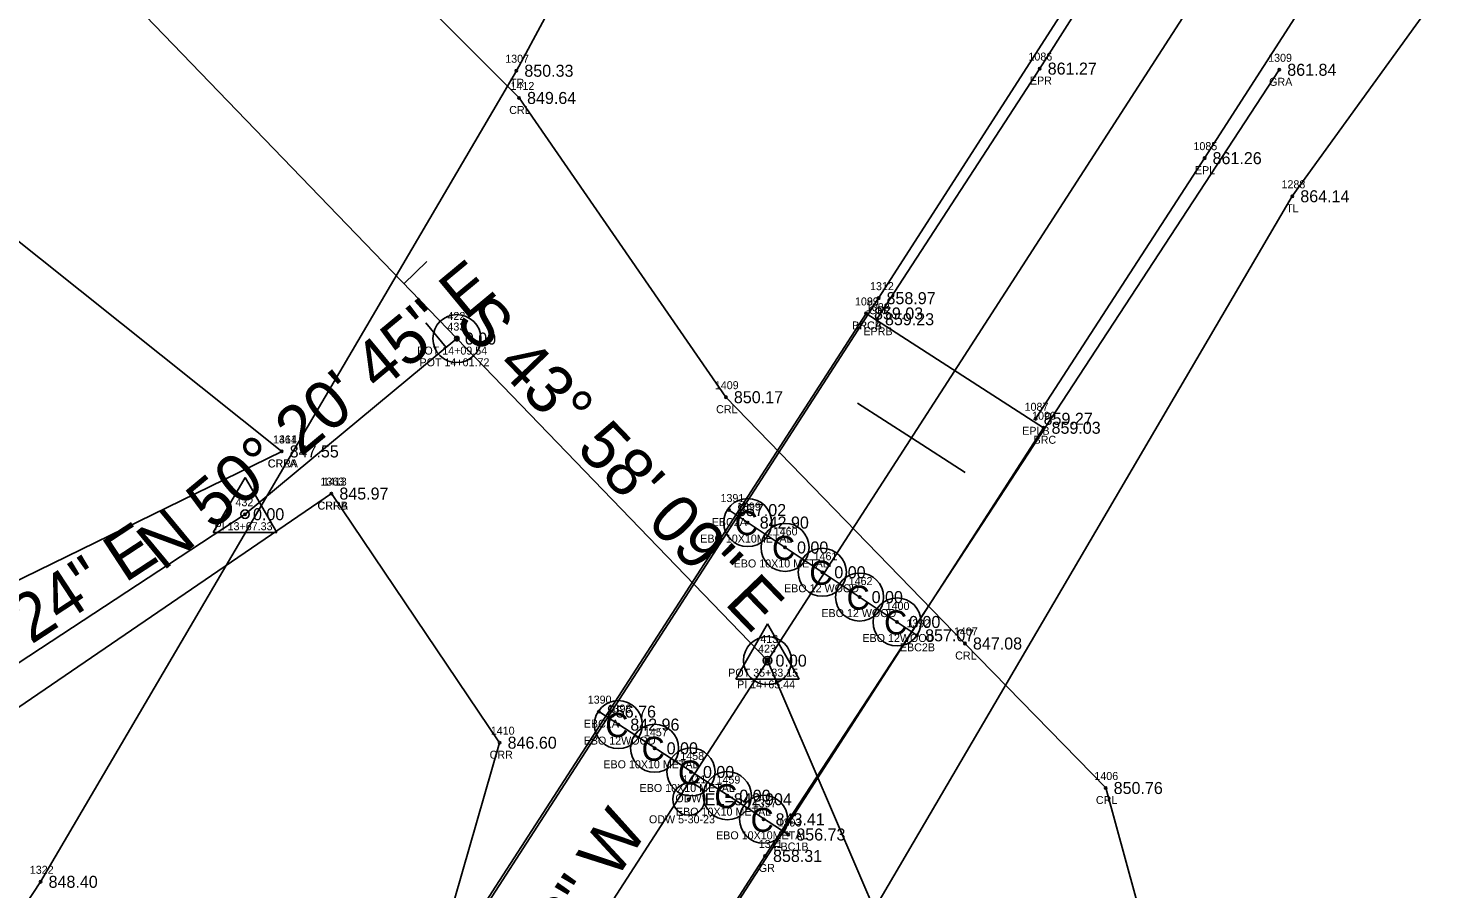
# Model space of a CAD drawing. Extents: x 1393163 to 1398407, y 1072670 to 1074651.
# Drawn here: x 1395829.2 to 1396005.3, y 1073941.1 to 1074048.6 of the extents above; entities that cross this region are included whole.
import ezdxf

# ---------------------------------------------------------------- set-up
doc = ezdxf.new("R2010")
doc.units = 0
for name, color, linetype in [('RD_EX_Bridge', 7, 'Continuous'), ('RD_EX_Bridge_txCode', 7, 'Continuous'), ('RD_EX_GuardRail', 7, 'Continuous'), ('RD_EX_GuardRail_txCode', 7, 'Continuous'), ('RD_EX_H2O', 7, 'Continuous'), ('RD_EX_H2O_txCode', 7, 'Continuous'), ('RD_EX_Road', 7, 'Continuous'), ('RD_EX_Road_txCode', 7, 'Continuous'), ('RD_EX_TX_Bridge_ELEV', 7, 'Continuous'), ('RD_EX_TX_GuardRail_ELEV', 7, 'Continuous'), ('RD_EX_TX_H2O_ELEV', 7, 'Continuous'), ('RD_EX_TX_Road_ELEV', 7, 'Continuous'), ('RD_EX_TX_VEG_ELEV', 7, 'Continuous'), ('RD_EX_VEG', 7, 'Continuous'), ('RD_EX_VEG_txCode', 7, 'Continuous'), ('RD_HC_Cl', 7, 'Continuous'), ('RD_HC_Data', 7, 'Continuous'), ('RD_HC_Data_Tic', 7, 'Continuous'), ('RD_HC_Survey_ELEV', 7, 'Continuous'), ('RD_HC_txCode', 7, 'Continuous'), ('RD_SMD_Locator', 7, 'Continuous')]:
    doc.layers.add(name, color=color, linetype=linetype)

msp = doc.modelspace()

# ---------------------------------------------------------------- linework, layer by layer
at = {"layer": 'RD_EX_Bridge'}
for p, q in [((1395916.79, 1073988.44), (1395940.29, 1073972.79)), ((1395900.53, 1073963.26), (1395924.2, 1073947.91))]:
    msp.add_line(p, q, dxfattribs=at)
msp.add_lwpolyline([(1395933.91, 1074013), (1395956.09, 1073998.72), (1395891.08, 1073897.92), (1395868.85, 1073912.35), (1395933.91, 1074013)], dxfattribs=at)
for centre in [(1395919.13, 1073986.88), (1395923.79, 1073983.77), (1395928.45, 1073980.67), (1395933.11, 1073977.57), (1395937.79, 1073974.46), (1395902.96, 1073961.64), (1395907.5, 1073958.68), (1395912.04, 1073955.72), (1395916.58, 1073952.76), (1395921.11, 1073949.81)]:
    msp.add_circle(centre, 3, dxfattribs=at)
at = {"layer": 'RD_EX_GuardRail'}
for points in [[(1396016.92, 1074142.31), (1395982.2, 1074087.63), (1395935.47, 1074014.91), (1395869.54, 1073912.84), (1395852.29, 1073888.13)], [(1395985.54, 1074043.44), (1395921.29, 1073945.23), (1395889.11, 1073895.32), (1395862.94, 1073850.57)]]:
    msp.add_lwpolyline(points, dxfattribs=at)
at = {"layer": 'RD_EX_H2O'}
for points in [[(1395994.31, 1073862.14), (1395977.4, 1073904.27), (1395963.85, 1073953.72), (1395946.27, 1073971.77), (1395916.4, 1074002.54), (1395890.56, 1074039.92), (1395847.47, 1074083.11), (1395801.13, 1074111.33), (1395786.04, 1074175.28), (1395797.31, 1074211.4), (1395811.45, 1074270.55), (1395842.05, 1074318.44), (1395857.75, 1074334.75)], [(1395860.9, 1073995.76), (1395815.67, 1074031.86), (1395776.21, 1074053.68), (1395741.83, 1074102.21), (1395737.14, 1074094.97), (1395730.93, 1074079.84), (1395706.27, 1074079.36), (1395688.76, 1074107.43)], [(1395860.9, 1073995.76), (1395800.01, 1073966.01), (1395776.82, 1073934.08), (1395764.26, 1073892.72), (1395729.42, 1073844.79)], [(1395867.11, 1073990.5), (1395809.63, 1073951.26), (1395794.76, 1073924.94), (1395779.33, 1073882.65), (1395735.99, 1073839.85)], [(1395952, 1073840.27), (1395936.35, 1073875.41), (1395908.33, 1073913.75), (1395880.62, 1073933.3), (1395888.13, 1073959.38), (1395867.11, 1073990.5)]]:
    msp.add_lwpolyline(points, dxfattribs=at)
for radius in [2, 0.15]:
    msp.add_circle((1395911.76, 1073952.31), radius, dxfattribs=at)
at = {"layer": 'RD_EX_Road'}
for points in [[(1396674.59, 1074386.64), (1396624.89, 1074395.26), (1396571.56, 1074398.48), (1396522.78, 1074397.7), (1396472.45, 1074394.9), (1396421.62, 1074390.65), (1396372.56, 1074384.52), (1396322.77, 1074374.54), (1396273.68, 1074359.26), (1396227.22, 1074339.05), (1396181.9, 1074313.32), (1396140.46, 1074283.11), (1396103.05, 1074249.25), (1396069.12, 1074211.4), (1396038.71, 1074171.59), (1396010.56, 1074129.17), (1395983.61, 1074087.64), (1395955.61, 1074043.59), (1395935.28, 1074012.28)], [(1396669.99, 1074363.58), (1396621.68, 1074371.65), (1396572.56, 1074374.92), (1396523.47, 1074374.03), (1396473.59, 1074371.37), (1396424.21, 1074367.31), (1396376.75, 1074361.05), (1396328.97, 1074351.54), (1396282.26, 1074337.09), (1396237.6, 1074317.67), (1396195.62, 1074293.72), (1396156.18, 1074264.82), (1396120.35, 1074232.59), (1396087.8, 1074196.98), (1396058.13, 1074158.17), (1396030.89, 1074117.17), (1396003.36, 1074074.62), (1395976.21, 1074032.4), (1395955.1, 1073999.84)]]:
    msp.add_lwpolyline(points, dxfattribs=at)
at = {"layer": 'RD_EX_VEG'}
for points in [[(1396352.77, 1074466.81), (1396307.45, 1074411.54), (1396264.81, 1074389.13), (1396223.65, 1074377.38), (1396189.41, 1074374.79), (1396152.48, 1074363.91), (1396104.93, 1074328.72), (1396084.67, 1074294.89), (1396058.15, 1074258), (1396032.64, 1074208.26), (1395942.76, 1074111.4), (1395907.95, 1074076.23), (1395890.22, 1074043.32), (1395830.78, 1073942), (1395722.32, 1073776.86), (1395650.71, 1073693.74), (1395598.01, 1073628.59), (1395527.38, 1073544.13)], [(1396669.03, 1074354.22), (1396616.02, 1074355.85), (1396573.77, 1074355.35), (1396526.61, 1074357.18), (1396479.56, 1074337.11), (1396434.19, 1074332.46), (1396381.24, 1074326.22), (1396336.08, 1074320.75), (1396275.81, 1074321.18), (1396244.15, 1074304.15), (1396202.15, 1074284.28), (1396132.57, 1074226.35), (1396098.86, 1074188.29), (1396070.36, 1074149.88), (1396041.42, 1074108.96), (1396016.11, 1074067.71), (1395987.17, 1074027.64), (1395903.34, 1073884.68), (1395772.36, 1073685.07), (1395714.36, 1073607.99), (1395678.43, 1073565.6), (1395644.57, 1073530.52), (1395600.99, 1073489.29), (1395561.12, 1073435.87)]]:
    msp.add_lwpolyline(points, dxfattribs=at)
at = {"layer": 'RD_HC_Cl'}
for p, q in [((1396041.52, 1074155.31), (1395744.21, 1073694.97)), ((1395765.48, 1074131.47), (1395882.79, 1074009.86)), ((1395856.32, 1073987.92), (1395882.79, 1074009.86)), ((1395882.79, 1074009.86), (1395921.6, 1073969.63)), ((1395794.66, 1073947.5), (1395856.32, 1073987.92)), ((1395921.6, 1073969.63), (1395997.49, 1073792.99))]:
    msp.add_line(p, q, dxfattribs=at)
at = {"layer": 'RD_HC_Data'}
for p, q in [((1395852.34, 1073985.62), (1395856.32, 1073992.5)), ((1395856.32, 1073992.5), (1395860.29, 1073985.62)), ((1395852.34, 1073985.62), (1395860.29, 1073985.62)), ((1395917.63, 1073967.33), (1395921.6, 1073974.21)), ((1395921.6, 1073974.21), (1395925.57, 1073967.33)), ((1395917.63, 1073967.33), (1395925.57, 1073967.33))]:
    msp.add_line(p, q, dxfattribs=at)
for centre, radius in [((1395882.79, 1074009.86), 3), ((1395882.79, 1074009.86), 3), ((1395882.79, 1074009.86), 0.282), ((1395882.79, 1074009.86), 0.282), ((1395856.32, 1073987.92), 0.529), ((1395921.6, 1073969.63), 3), ((1395921.6, 1073969.63), 0.529), ((1395921.6, 1073969.63), 0.282)]:
    msp.add_circle(centre, radius, dxfattribs=at)
at = {"layer": 'RD_HC_Data_Tic'}
for p, q in [((1395876.17, 1074016.72), (1395879.05, 1074019.5)), ((1395881.47, 1074008.76), (1395878.92, 1074011.84)), ((1395939.58, 1073997.47), (1395932.86, 1074001.81)), ((1395939.58, 1073997.47), (1395946.3, 1073993.13))]:
    msp.add_line(p, q, dxfattribs=at)
at = {"layer": 'RD_SMD_Locator'}
for centre in [(1395890.22, 1074043.32), (1395955.61, 1074043.59), (1395985.54, 1074043.44), (1395890.56, 1074039.92), (1395976.21, 1074032.4), (1395987.17, 1074027.64), (1395935.47, 1074014.91), (1395933.91, 1074013), (1395933.91, 1074013), (1395935.28, 1074012.28), (1395882.79, 1074009.86), (1395882.79, 1074009.86), (1395916.4, 1074002.54), (1395955.1, 1073999.84), (1395956.09, 1073998.72), (1395860.9, 1073995.76), (1395860.9, 1073995.76), (1395867.11, 1073990.5), (1395867.11, 1073990.5), (1395856.32, 1073987.92), (1395916.79, 1073988.44), (1395919.13, 1073986.88), (1395923.79, 1073983.77), (1395928.45, 1073980.67), (1395933.11, 1073977.57), (1395937.79, 1073974.46), (1395940.29, 1073972.79), (1395946.27, 1073971.77), (1395921.6, 1073969.63), (1395921.6, 1073969.63), (1395900.53, 1073963.26), (1395902.96, 1073961.64), (1395888.13, 1073959.38), (1395907.5, 1073958.68), (1395912.04, 1073955.72), (1395916.58, 1073952.76), (1395963.85, 1073953.72), (1395921.11, 1073949.81), (1395924.2, 1073947.91), (1395921.29, 1073945.23), (1395830.78, 1073942)]:
    msp.add_circle(centre, 0.15, dxfattribs=at)

# ---------------------------------------------------------------- texts
at = {"layer": 'RD_EX_Bridge'}
for p in [(1395917.5, 1073985.32), (1395922.16, 1073982.21), (1395926.82, 1073979.11), (1395931.48, 1073976.01), (1395936.16, 1073972.9), (1395901.33, 1073960.08), (1395905.87, 1073957.12), (1395910.41, 1073954.16), (1395914.95, 1073951.2), (1395919.48, 1073948.24)]:
    msp.add_text('C', height=3, dxfattribs=at).set_placement(p)
at = {"layer": 'RD_EX_Bridge_txCode'}
for s, p in [('1089', (1395932.53, 1074014)), ('1093', (1395932.53, 1074014)), ('BRCA', (1395932.17, 1074011)), ('BRCB', (1395932.19, 1074011)), ('1090', (1395954.66, 1073999.72)), ('BRC', (1395954.84, 1073996.72)), ('1391', (1395915.73, 1073989.44)), ('1399', (1395917.78, 1073988.38)), ('EBC2A', (1395914.63, 1073986.44)), ('1460', (1395922.38, 1073985.27)), ('EBO 10X10METAL', (1395913.2, 1073984.38)), ('1461', (1395927.36, 1073982.17)), ('EBO 10X10 METAL', (1395917.37, 1073981.27)), ('EBO 12 WOOD', (1395923.67, 1073978.17)), ('1462', (1395931.74, 1073979.07)), ('EBO 12 WOOD', (1395928.33, 1073975.07)), ('1400', (1395936.36, 1073975.96)), ('1392', (1395938.95, 1073973.79)), ('EBO 12WOOD', (1395933.46, 1073971.96)), ('EBC2B', (1395938.14, 1073970.79)), ('1390', (1395899.14, 1073964.26)), ('1398', (1395901.62, 1073963.14)), ('EBC1A', (1395898.65, 1073961.26)), ('EBO 12WOOD', (1395898.63, 1073959.14)), ('1457', (1395906.16, 1073960.18)), ('1458', (1395910.7, 1073957.22)), ('EBO 10X10 METAL', (1395901.09, 1073956.18)), ('1459', (1395915.23, 1073954.26)), ('EBO 10X10 METAL', (1395905.62, 1073953.22)), ('EBO 10X10 METAL', (1395910.16, 1073950.26)), ('1397', (1395919.76, 1073951.31)), ('1393', (1395922.86, 1073948.91)), ('EBO 10X10METAL', (1395915.18, 1073947.31)), ('EBC1B', (1395922.34, 1073945.91))]:
    msp.add_text(s, height=1, dxfattribs=at).set_placement(p)
at = {"layer": 'RD_EX_GuardRail_txCode'}
for s, p in [('1309', (1395984.15, 1074044.44)), ('GRA', (1395984.27, 1074041.44)), ('1312', (1395934.41, 1074015.91)), ('GR2', (1395934.25, 1074012.91)), ('1311', (1395920.51, 1073946.23)), ('GR', (1395920.51, 1073943.23))]:
    msp.add_text(s, height=1, dxfattribs=at).set_placement(p)
at = {"layer": 'RD_EX_H2O'}
msp.add_text('ODW', height=1, dxfattribs=at).set_placement((1395910.09, 1073951.94))
at = {"layer": 'RD_EX_H2O_txCode'}
for s, p in [('1412', (1395889.49, 1074040.92)), ('CRL', (1395889.33, 1074037.92)), ('1409', (1395915.02, 1074003.54)), ('CRL', (1395915.18, 1074000.54)), ('1361', (1395859.81, 1073996.76)), ('1414', (1395859.83, 1073996.76)), ('CRRA', (1395859.15, 1073993.76)), ('CRLA', (1395859.18, 1073993.76)), ('1363', (1395865.74, 1073991.5)), ('1413', (1395866.05, 1073991.5)), ('CRRA', (1395865.37, 1073988.5)), ('CRRB', (1395865.39, 1073988.5)), ('1407', (1395944.89, 1073972.77)), ('CRL', (1395945.05, 1073969.77)), ('1410', (1395887.03, 1073960.38)), ('CRR', (1395886.88, 1073957.38)), ('1411', (1395910.98, 1073954.31)), ('1406', (1395962.44, 1073954.72)), ('CRL', (1395962.63, 1073951.72)), ('ODW 5-30-23', (1395906.79, 1073949.31))]:
    msp.add_text(s, height=1, dxfattribs=at).set_placement(p)
at = {"layer": 'RD_EX_Road_txCode'}
for s, p in [('1086', (1395954.2, 1074044.59)), ('EPR', (1395954.38, 1074041.59)), ('1085', (1395974.82, 1074033.4)), ('EPL', (1395975, 1074030.4)), ('1088', (1395933.89, 1074013.28)), ('EPRB', (1395933.58, 1074010.28)), ('1087', (1395953.72, 1074000.84)), ('EPLB', (1395953.42, 1073997.84))]:
    msp.add_text(s, height=1, dxfattribs=at).set_placement(p)
at = {"layer": 'RD_EX_TX_Bridge_ELEV'}
for s, p in [('859.03', (1395934.91, 1074012.25)), ('859.03', (1395934.91, 1074012.25)), ('859.03', (1395957.09, 1073997.97)), ('857.02', (1395917.79, 1073987.69)), ('842.90', (1395920.63, 1073986.13)), ('0.00', (1395925.29, 1073983.02)), ('0.00', (1395929.95, 1073979.92)), ('0.00', (1395934.61, 1073976.82)), ('0.00', (1395939.29, 1073973.71)), ('857.07', (1395941.29, 1073972.04)), ('856.76', (1395901.53, 1073962.51)), ('842.96', (1395904.46, 1073960.89)), ('0.00', (1395909, 1073957.93)), ('0.00', (1395913.54, 1073954.97)), ('0.00', (1395918.08, 1073952.01)), ('843.41', (1395922.61, 1073949.06)), ('856.73', (1395925.2, 1073947.16))]:
    msp.add_text(s, height=1.5, dxfattribs=at).set_placement(p)
at = {"layer": 'RD_EX_TX_GuardRail_ELEV'}
for s, p in [('861.84', (1395986.54, 1074042.69)), ('858.97', (1395936.47, 1074014.16)), ('858.31', (1395922.29, 1073944.48))]:
    msp.add_text(s, height=1.5, dxfattribs=at).set_placement(p)
at = {"layer": 'RD_EX_TX_H2O_ELEV'}
for s, p in [('849.64', (1395891.56, 1074039.17)), ('850.17', (1395917.4, 1074001.79)), ('847.55', (1395861.9, 1073995.01)), ('847.55', (1395861.9, 1073995.01)), ('845.97', (1395868.11, 1073989.75)), ('845.97', (1395868.11, 1073989.75)), ('847.08', (1395947.27, 1073971.02)), ('846.60', (1395889.13, 1073958.63)), ('850.76', (1395964.85, 1073952.97)), ('EL=842.904', (1395913.76, 1073951.56))]:
    msp.add_text(s, height=1.5, dxfattribs=at).set_placement(p)
at = {"layer": 'RD_EX_TX_Road_ELEV'}
for s, p in [('861.27', (1395956.61, 1074042.84)), ('861.26', (1395977.21, 1074031.65)), ('859.23', (1395936.28, 1074011.53)), ('859.27', (1395956.1, 1073999.09))]:
    msp.add_text(s, height=1.5, dxfattribs=at).set_placement(p)
at = {"layer": 'RD_EX_TX_VEG_ELEV'}
for s, p in [('850.33', (1395891.22, 1074042.57)), ('864.14', (1395988.17, 1074026.89)), ('848.40', (1395831.78, 1073941.25))]:
    msp.add_text(s, height=1.5, dxfattribs=at).set_placement(p)
at = {"layer": 'RD_EX_VEG_txCode'}
for s, p in [('1307', (1395888.83, 1074044.32)), ('TR', (1395889.42, 1074041.32)), ('1288', (1395985.82, 1074028.64)), ('TL', (1395986.39, 1074025.64)), ('1322', (1395829.43, 1073943))]:
    msp.add_text(s, height=1, dxfattribs=at).set_placement(p)
at = {"layer": 'RD_HC_Data'}
for s, rotation, p in [('N 50%%d 20\' 45" E', 39.6543, (1395846.05, 1073980.71)), ('S 43%%d 58\' 09" E', 313.9692, (1395882.33, 1074011.77)), ('N 56%%d 45\' 24" E', 33.2434, (1395800.27, 1073952.37)), ('S 32%%d 51\' 23" W', 57.1437, (1395876.23, 1073901.21))]:
    msp.add_text(s, height=6, rotation=rotation, dxfattribs=at).set_placement(p)
at = {"layer": 'RD_HC_Survey_ELEV'}
for p in [(1395883.79, 1074009.11), (1395883.79, 1074009.11), (1395857.32, 1073987.17), (1395922.6, 1073968.88), (1395922.6, 1073968.88)]:
    msp.add_text('0.00', height=1.5, dxfattribs=at).set_placement(p)
at = {"layer": 'RD_HC_txCode'}
for s, p in [('422', (1395881.61, 1074012.18)), ('433', (1395881.61, 1074010.86)), ('POT 14+09.54', (1395877.84, 1074007.86)), ('POT 14+01.72', (1395878.12, 1074006.4)), ('432', (1395855.13, 1073988.92)), ('PI 13+67.33', (1395852.51, 1073985.92)), ('413', (1395920.7, 1073971.84)), ('423', (1395920.42, 1073970.63)), ('POT 35+33.15', (1395916.69, 1073967.63)), ('PI 14+65.44', (1395917.8, 1073966.17))]:
    msp.add_text(s, height=1, dxfattribs=at).set_placement(p)

doc.saveas('drawing.dxf')
